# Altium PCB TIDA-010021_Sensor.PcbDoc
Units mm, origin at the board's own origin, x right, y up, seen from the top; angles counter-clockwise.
Board outline 22 x 20 mm, 4 copper layers (Top Layer, Signal Layer 1, Signal Layer 2, Bottom Layer), stack 1.647 mm thick; 35 components, 19 nets, 95 pads, 93 vias.
Unrouted connection lines stored in the file: 42.
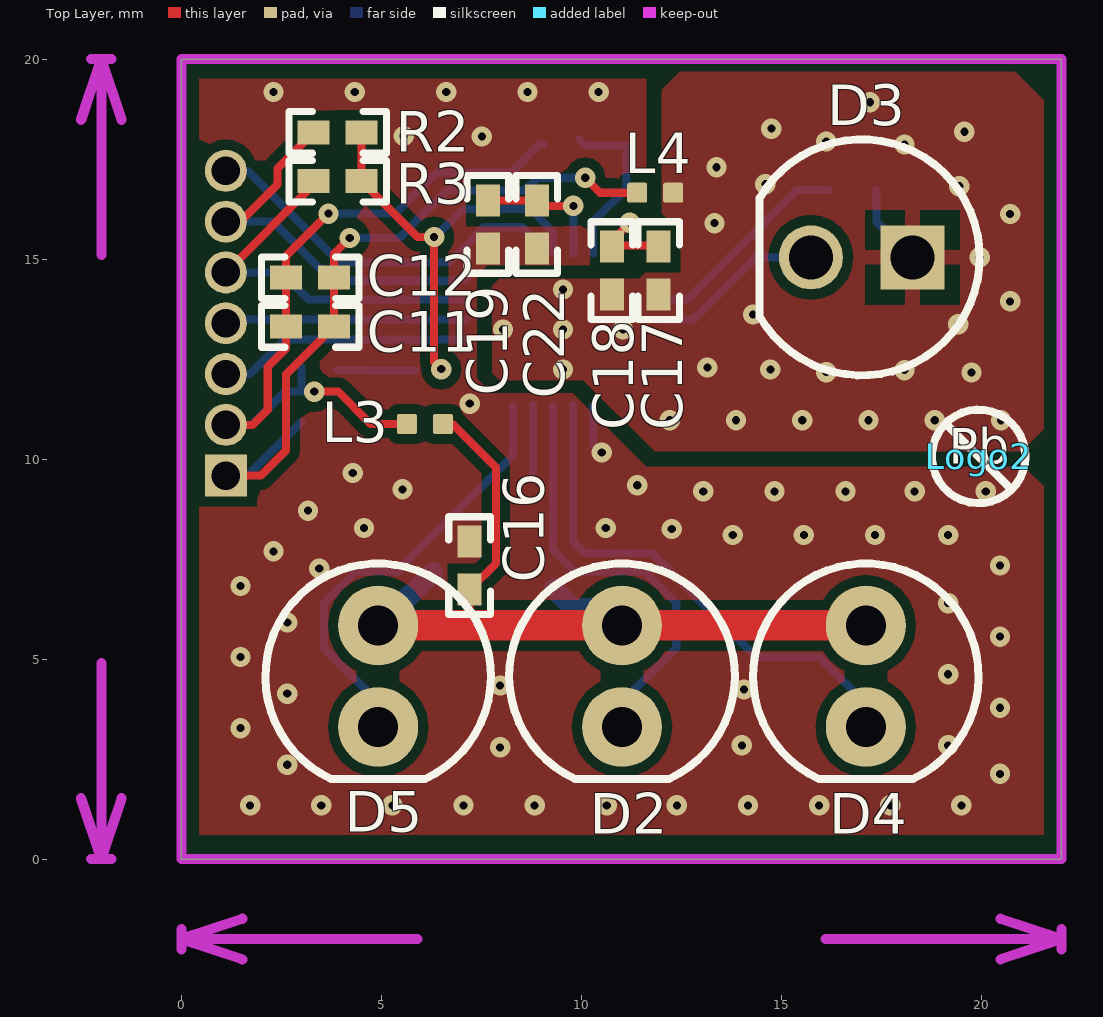
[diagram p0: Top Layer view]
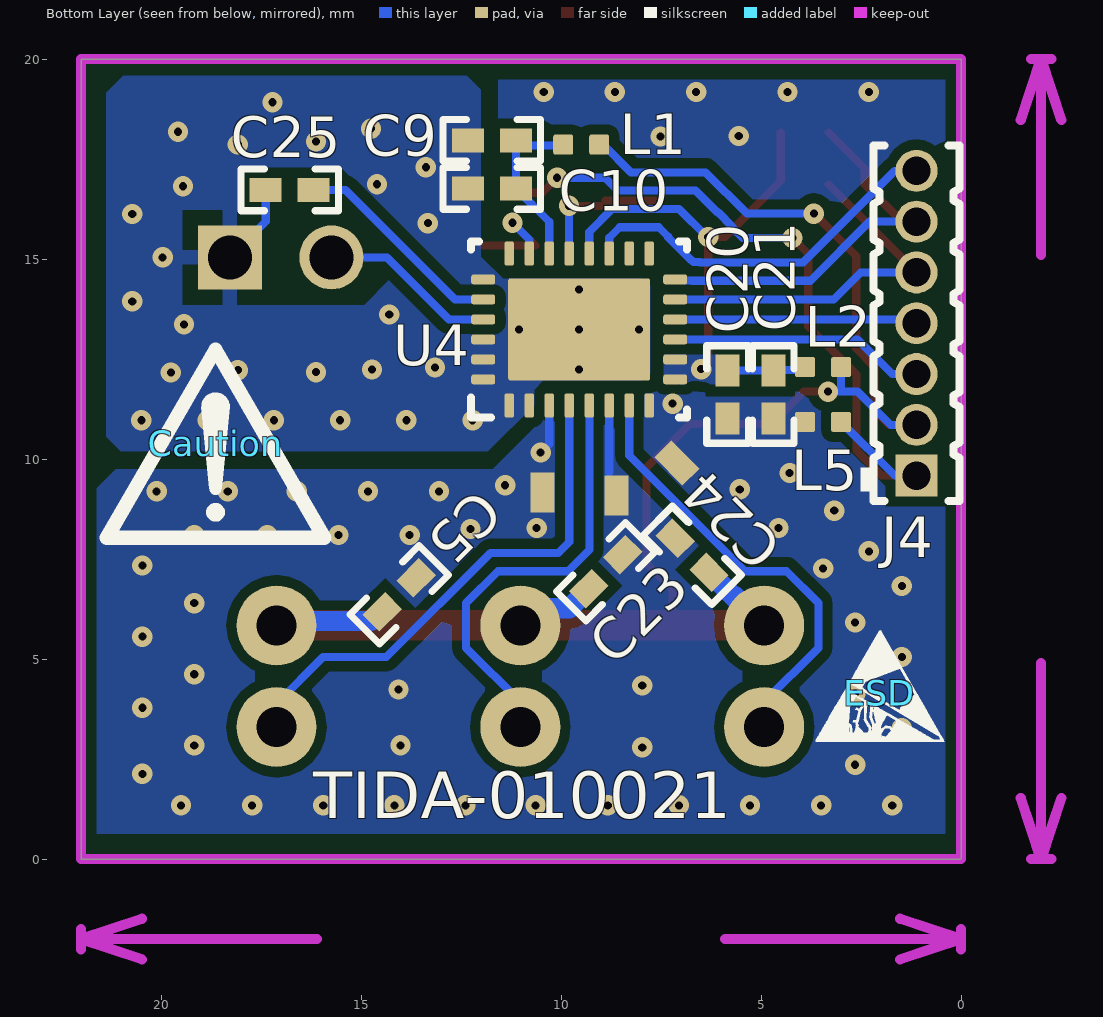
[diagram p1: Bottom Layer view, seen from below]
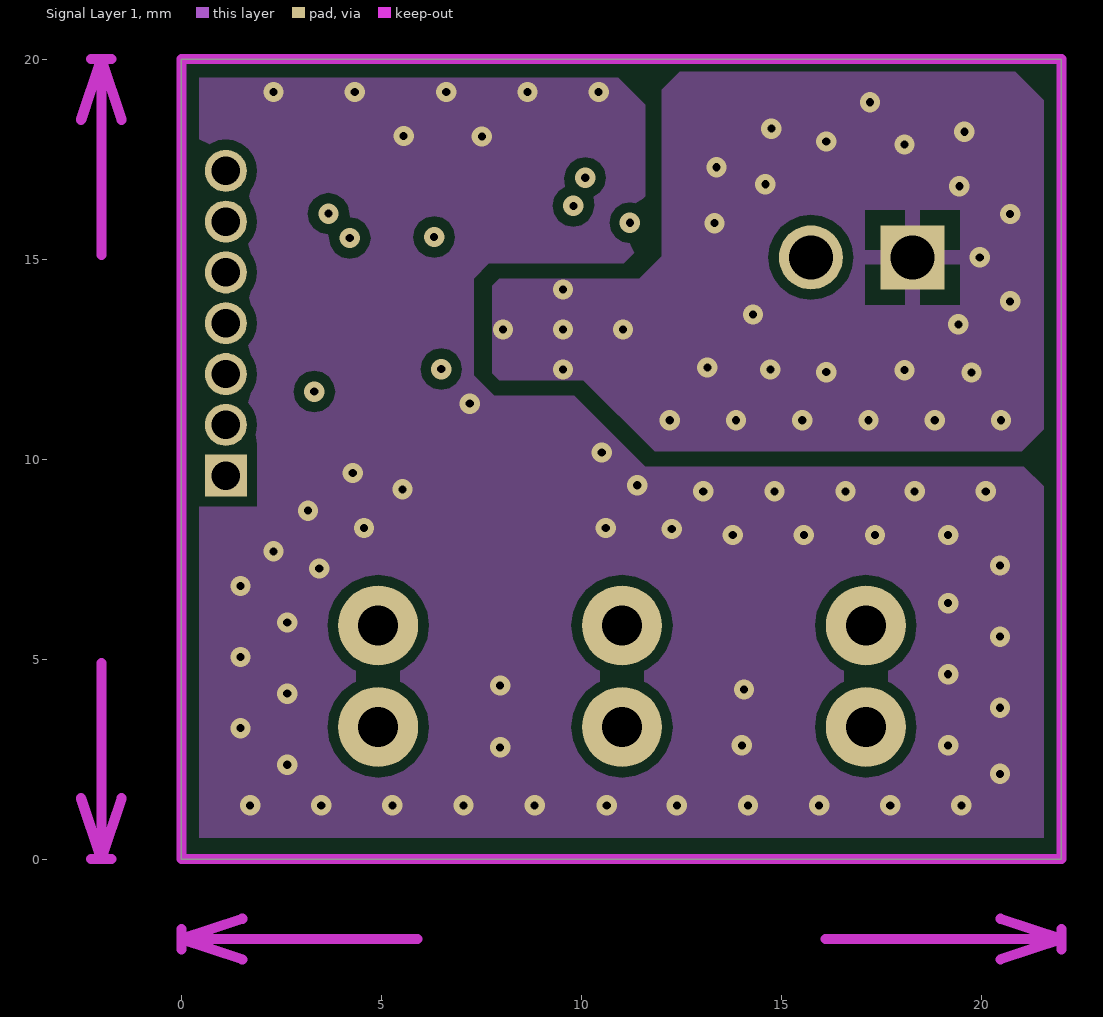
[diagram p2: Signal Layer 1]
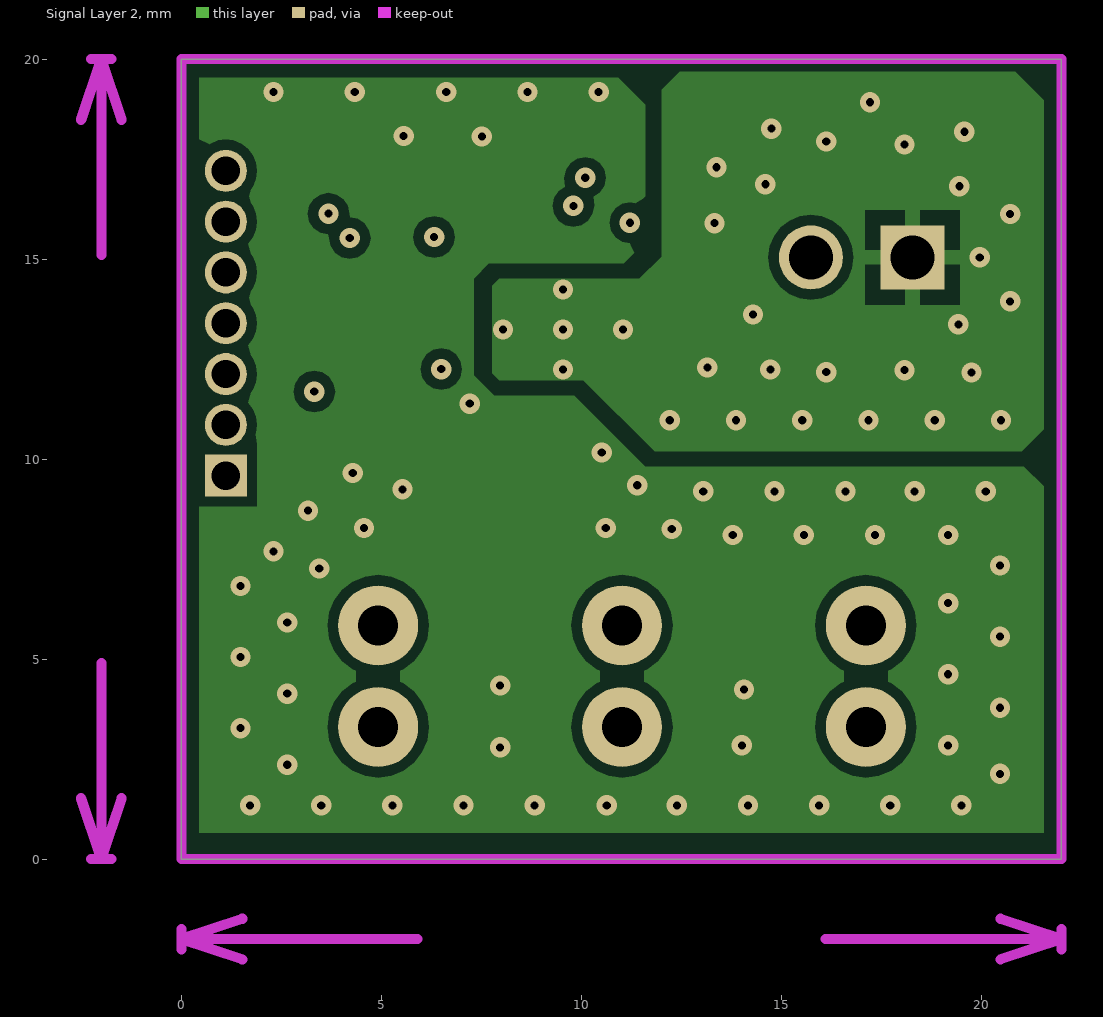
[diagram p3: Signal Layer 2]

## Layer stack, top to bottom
Top Solder: solder mask 0.0102, Solder Resist, Dk 3.5
Top Layer: signal copper 0.0356
Dielectric1: core 1.5037, FR-4, Dk 4.8
Signal Layer 1: signal copper 0.036
Signal Layer 2: signal copper 0.036
Bottom Layer: signal copper 0.0356
Bottom Solder: solder mask 0.0102, Solder Resist, Dk 3.5

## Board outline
0,0 0,20 22,20 22,0

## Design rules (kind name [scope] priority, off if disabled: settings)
AcuteAngle [All] p1: minimum=4.50000000000000E+0001 checktracksonly=FALSE
AssemblyTestPointUsage [All] p1: valid=2
BoardOutlineClearance BoardOutlineClearance_MountingHoles [OnCopper and InComponentClass('Mounting Holes')] p1: gap=1.016
BoardOutlineClearance BoardOutlineClearance_Poly [OnCopper and IsPoly] p2: gap=0.635
BoardOutlineClearance [OnCopper and Not InComponentClass('Logo') and not InComponentClass('FiducialMark') and not InRegion(1000,500,4000,800) and not InPoly] p3: gap=1.905
Clearance Clearance_Keepouts [((IsTrack Or IsArc) And Not InPoly) And IsFree and IsKeepOut vs ((IsTrack Or IsArc) And Not InPoly) And IsFree and IsKeepOut] p1: gap=0.254
Clearance Clearance_Poly [InPolygon] p2: gap=0.254
Clearance [All] p3: gap=0.254
ComponentClearance ComponentClearance_MountingHoles_FiducialMarks [InComponentClass('Mounting Holes') vs InComponentClass('FiducialMark')] p1: gap=1.27 collisioncheckmode=3 verticalgap=0.254 showdistances=FALSE
ComponentClearance ComponentClearance_Shunt [InComponentClass('Header') vs InComponentClass('Shunt')] p2: gap=0 collisioncheckmode=3 verticalgap=0 showdistances=FALSE
ComponentClearance ComponentClearance_Logo [InComponentClass('Logo')] p3: gap=1.27 collisioncheckmode=3 verticalgap=0.254 showdistances=FALSE
ComponentClearance ComponentClearance_ScrewToNut [(HasFootprint('NY PMS 440 0025 PH')) vs (HasFootprint('Keystone_1902C'))] p4: gap=0.127 collisioncheckmode=3 verticalgap=0.254 showdistances=FALSE
ComponentClearance ComponentClearance_MountingHoles [InComponentClass('Mounting Holes')] p5: gap=6.35 collisioncheckmode=3 verticalgap=2540 showdistances=FALSE
ComponentClearance ComponentClearance_SmallPassives [HasFootprint('0201*') or HasFootprint('0402*') or HasFootprint('0508') or HasFootprint('0603*') or HasFootprint('0612') or HasFootprint('0805*') or HasFootprint('0815*') or HasFootprint('0830*') or HasFootprint('1206*') or HasFootprint('1210*') or HasFootprint('1808*') or HasFootprint('1812*') or HasFootprint('1825*') or HasFootprint('2010*') or HasFootprint('2220*') or HasFootprint('2225*') or HasFootprint('2512*') or HasFootprint('2728*') or HasFootprint('3518*') vs HasFootprint('0201*') or HasFootprint('0402*') or HasFootprint('0508') or HasFootprint('0603*') or HasFootprint('0612') or HasFootprint('0805*') or HasFootprint('0815*') or HasFootprint('0830*') or HasFootprint('1206*') or HasFootprint('1210*') or HasFootprint('1808*') or HasFootprint('1812*') or HasFootprint('1825*') or HasFootprint('2010*') or HasFootprint('2220*') or HasFootprint('2225*') or HasFootprint('2512*') or HasFootprint('2728*') or HasFootprint('3518*')] p6: gap=0.38 collisioncheckmode=3 verticalgap=0.254 showdistances=FALSE
ComponentClearance ComponentClearance_THtoSMT [IsThruComponent vs IsSMTComponent] p7: gap=1.016 collisioncheckmode=3 verticalgap=0.762 showdistances=FALSE
ComponentClearance ComponentClearance_THtoTH [IsThruComponent vs IsThruComponent] p8: gap=0.762 collisioncheckmode=3 verticalgap=0.762 showdistances=FALSE
ComponentClearance [All] p9: gap=0.762 collisioncheckmode=3 verticalgap=0.254 showdistances=FALSE
DiffPairsRouting [All] p1: maxlimit=2.54 minlimit=0.254 mostfreqgap=0.254 toplayer_minwidth=0.381 toplayer_maxwidth=0.381 toplayer_prefwidth=0.381 midlayer1_minwidth=0.381 midlayer1_maxwidth=0.381 midlayer1_prefwidth=0.381 midlayer2_minwidth=0.381 midlayer2_maxwidth=0.381 midlayer2_prefwidth=0.381 bottomlayer_minwidth=0.381 bottomlayer_maxwidth=0.381 bottomlayer_prefwidth=0.381 maxuncoupledlength=25.4
FabricationTestPointUsage TestPointUsage [All] p1: valid=2 allowmultiple=FALSE
FabricationTestpoint Testpoint [All] p1: side=3 testpointundercomponent=TRUE minsize=1.016 maxsize=2.54 preferedsize=1.524 minholesize=0 maxholesize=1.016 preferedholesize=0.813 testpointgrid=0.025 allowsidetop=TRUE allowsidebottom=TRUE usegrid=TRUE gridtolerance=0
FanoutControl Fanout_LCC [IsLCC] p1: bgadir=Out bgaviamode=Centered fanoutstyle=Auto fanoutdirection=Alternating viagrid=0.025 // Fanout_LCC (Default Rule)
FanoutControl Fanout_BGA [IsBGA] p2: bgadir=Out bgaviamode=Centered fanoutstyle=Auto fanoutdirection=Alternating viagrid=0.025 // Fanout_BGA (Default Rule)
FanoutControl Fanout_Default [All] p4: bgadir=Out bgaviamode=Centered fanoutstyle=Auto fanoutdirection=Alternating viagrid=0.025 // Fanout_Default (Default Rule)
FanoutControl Fanout_Small [(CompPinCount < 5)] p5: bgadir=Out bgaviamode=Centered fanoutstyle=Auto fanoutdirection=OutThenIn viagrid=0.025 // Fanout_Small (Default Rule)
HoleSize [All] p1: absolutevalues=TRUE maxlimit=6.375 minlimit=0.2 maxpercent=80.000 minpercent=20.000
MinimumAnnularRing MinimumAnnularRing_ThermalPadVias [IsVia and InAnyComponent] p1: minimumring=0.15
MinimumAnnularRing [All] p2: minimumring=0.203
MinimumSolderMaskSliver MinimumSolderMaskSliver_Logo [InComponentClass('Logo') vs InComponentClass('Logo')] p1: minsoldermaskwidth=0.018
MinimumSolderMaskSliver [All] p2: minsoldermaskwidth=0.1
PlaneClearance [All] p1: clearance=0.381
PlaneConnect [All] p1: planeconnectstyle=Relief reliefexpansion=0.254 reliefentries=4 reliefconductorwidth=0.381 reliefairgap=0.381
PolygonConnect PolygonConnect_1 [IsPadHoleValid] p1: connectstyle=Direct reliefconductorwidth=0.381 reliefentries=4 polygonreliefangle="90 Angle" airgapwidth=0.381
PolygonConnect PolygonConnect_Via [IsVia] p2: connectstyle=Direct reliefconductorwidth=0.254 reliefentries=4 polygonreliefangle="90 Angle" airgapwidth=0.254
PolygonConnect [Ispad] p3: connectstyle=Direct reliefconductorwidth=0.381 reliefentries=4 polygonreliefangle="90 Angle" airgapwidth=0.381
RoutingVias ThermalPadVias [IsVia and InAnyComponent] p1: holewidth=0.2 width=0.5 viastyle="Through Hole" minholewidth=0.2 minwidth=0.5 maxholewidth=0.33 maxwidth=0.6
RoutingVias [All] p2: holewidth=0.406 width=0.864 viastyle="Through Hole" minholewidth=0.2 minwidth=0.66 maxholewidth=1.016 maxwidth=1.651
SilkToBoardRegionClearance [Not ((IsComment or IsDesignator) And (Hide <> 'False')) and not InRegion(1000,500,4000,800)] p1:
SilkToSilkClearance SilkToSilkClearance_Pb-FreeLogo [(HasFootprint('Pb-Free_Overlay_Medium') OR HasFootprint('Pb-Free_Overlay_Small')) vs (HasFootprint('Pb-Free_Overlay_Medium') OR HasFootprint('Pb-Free_Overlay_Small'))] p1: silktosilkclearance=0
SilkToSilkClearance [All] p2: silktosilkclearance=0.102
SilkToSolderMaskClearance SilkToComponentPadClearance [(IsPad or IsFill or IsRegion) and InAnycomponent] p1: minsilkscreentomaskgap=0.127 clearancetoexposedcopper=TRUE
SilkToSolderMaskClearance "Silk to Solder Mask Opening" [All] p2: minsilkscreentomaskgap=0.102 clearancetoexposedcopper=FALSE
SolderMaskExpansion [All] p1: expansion=0.05
Width [All] p1: maxlimit=2.54 minlimit=0.152 preferedwidth=0.254 checkconnectedcopper=TRUE
14 further rules are at their usual default settings.

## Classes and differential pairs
component class Header: J4
component class TIDA-010021_Sensor: C5 C9 C10 C11 C12 C16 C17 C18 C19 C20 C21 C22 C23 C24 C25 D2 D3 D4 D5 J4 L1 L2 L3 L4 L5 R2 R3 U4
component class TIDA-010021_Sensor_Hardware: Caution ESD Logo2 ZZ1 ZZ2 ZZ3 ZZ4
component class AssemblyNote: ZZ1 ZZ2 ZZ3 ZZ4

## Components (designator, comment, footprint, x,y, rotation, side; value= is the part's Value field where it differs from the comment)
C5 "885012205037" 0402 14.046,6.604 r135 bottom
C9 "885012205037" 0402 11.729,17.967 r0 bottom
C10 "GRM155R61A105KE15D" 0402 11.73,16.765 r0 bottom
C11 "885012205037" 0402 3.219,13.316 r0 top
C12 "GRM155R61A105KE15D" 0402 3.219,14.535 r0 top
C16 "GRM155R61A105KE15D" 0402 7.207,7.337 r90 top
C17 "885012205037" 0402 11.933,14.712 r90 top
C18 "GRM155R61A105KE15D" 0402 10.765,14.712 r90 top
C19 "GRM155R61A105KE15D" 0402 7.666,15.865 r90 top
C20 "885012205037" 0402 5.837,11.613 r90 bottom
C21 "GRM155R61A105KE15D" 0402 4.694,11.613 r90 bottom
C22 "885012205037" 0402 8.887,15.865 r90 top
C23 "885012205037" 0402 8.883,7.185 r135 bottom
C24 "885012205037" 0402 6.724,7.591 r45 bottom
C25 "GRM1555C1E6R2CA01D" 0402 16.783,16.729 r0 bottom
Caution "CAUTION.  READ USER GUIDE BEFORE USE" IEC_Caution_small 18.637,10.395 r180 bottom
D2 "SFH 4556" SFH4556 11.017,4.569 r270 top
D3 "SFH 213" SFH_213 17.009,15.042 r180 top
D4 "SFH 4556" SFH4556 17.113,4.569 r270 top
D5 "SFH 4556" SFH4556 4.921,4.569 r270 top
ESD "ESD Susceptible" ESD_Overlay_small 2.051,4.156 r180 bottom
J4 "FTS-107-01-F-S" Samtec_FTS-107-01-x-S 1.113,13.395 r90 bottom
L1 "MMZ1005S182ET000" MMZ1005-E 9.495,17.862 r0 bottom
L2 "MMZ1005S182ET000" MMZ1005-E 3.449,12.299 r0 bottom
L3 "MMZ1005S182ET000" MMZ1005-E 6.091,10.877 r0 top
L4 "MMZ1005S182ET000" MMZ1005-E 11.848,16.658 r0 top
L5 "MMZ1005S182ET000" MMZ1005-E 3.449,10.927 r0 bottom
Logo2 "Pb-Free Symbol" Pb-Free_Overlay_Small 19.932,10.064 r0 top
R2 "RC0402FR-072K2L" 0402 3.907,18.166 r180 top
R3 "RC0402FR-072K2L" 0402 3.907,16.947 r180 top
U4 "OPT3101RHFR" RHF0028A 9.545,13.239 r90 bottom
ZZ1 "This Assembly Note is for PCB labels only" AssemblyNoteLabel -5.027,66.785 r0 top
ZZ2 "These assemblies are ESD sensitive, ESD precautions shall be observed." AssemblyNote -5.027,64.02 r0 top
ZZ3 "These assemblies must be clean and free from flux and all contaminants. Use of no clean flux is not acceptable." AssemblyNote -5.027,61.77 r0 top
ZZ4 "These assemblies must comply with workmanship standards IPC-A-610 Class 2, unless otherwise specified." AssemblyNote -5.027,59.521 r0 top

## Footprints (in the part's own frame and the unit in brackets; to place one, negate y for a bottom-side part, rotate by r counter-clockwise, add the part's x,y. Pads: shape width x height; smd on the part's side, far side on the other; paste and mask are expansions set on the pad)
0402 [mm] "0402 from SM-752 data"
  rect 0.8x0.6 smd: 1(-0.6,0) 2(0.6,0)
  silkscreen extent -1.22,-0.52 1.22,0.52, body extent -0.55,-0.3 0.55,0.3, height 0.6
AssemblyNote [mm] "Assembly Note"
AssemblyNoteLabel [mm] "Assembly Note for PCB Labels"
ESD_Overlay_small [mm]
  silkscreen extent -1.58,-1.23 1.62,1.55
IEC_Caution_small [mm]
  silkscreen extent -2.72,-2.36 2.72,2.35
MMZ1005-E [mm] "SMD, 2-Leads, Body 1x0.5mm"
  rrect20% 0.5x0.5 smd: 1(-0.45,0) 2(0.45,0)
  body extent -0.53,-0.28 0.53,0.28, height 0.55
Pb-Free_Overlay_Small [mm]
  silkscreen extent -1.16,-1.17 1.17,1.17
RHF0028A [mm] "QFN, 28-Leads, Body 5x4mm, Pitch 0.5mm, Thermal Pad 3.55x2.55mm"
  rrect42% 0.6x0.24 smd: 1(-1.9,1.75) 2(-1.9,1.25) 3(-1.9,0.75) 4(-1.9,0.25) 5(-1.9,-0.25) 6(-1.9,-0.75) 7(-1.9,-1.25) 8(-1.9,-1.75) 15(1.9,-1.75) 16(1.9,-1.25) 17(1.9,-0.75) 18(1.9,-0.25) 19(1.9,0.25) 20(1.9,0.75) 21(1.9,1.25) 22(1.9,1.75)
  rrect42% 0.24x0.6 smd: 9(-1.25,-2.4) 10(-0.75,-2.4) 11(-0.25,-2.4) 12(0.25,-2.4) 13(0.75,-2.4) 14(1.25,-2.4) 23(1.25,2.4) 24(0.75,2.4) 25(0.25,2.4) 26(-0.25,2.4) 27(-0.75,2.4) 28(-1.25,2.4)
  rrect9% 1.13x1.53 on Bottom Paste: 29(-0.665,-0.865) 29(-0.665,0.865) 29(0.665,-0.865) 29(0.665,0.865)
  rrect4% 2.55x3.55 smd paste-3.55: 29(0,0)
  silkscreen extent -2.2,-2.7 2.2,2.7, body extent -2,-2.5 2,2.5, height 1
Samtec_FTS-107-01-x-S [mm] "Header, 1.27 mm, 7x1, TH"
  rect 1.05x1.05 hole 0.71: 1(-3.81,0)
  round 1.05 hole 0.71: 2(-2.54,0) 3(-1.27,0) 4(0,0) 5(1.27,0) 6(2.54,0) 7(3.81,0)
  silkscreen extent -4.45,-1.08 4.45,1.4, body extent -4.44,-1.08 4.45,1.08, height 3.91
SFH4556 [mm] "TH, 2-Leads, Dia 5.5mm, Pin Spacing 2.54mm"
  round 2 hole 1: 1(-1.27,0) 2(1.27,0)
  silkscreen extent -2.82,-2.82 2.57,2.82, body extent -2.75,-2.75 2.5,2.75, height 10.7
SFH_213 [mm] "TH, 2-Leads, Dia 5.7mm, Pin Spacing 2.54mm"
  rect 1.6x1.6 hole 1.1: 1(-1.27,0)
  round 1.6 hole 1.1: 2(1.27,0)
  silkscreen extent -2.95,-2.95 2.55,2.95, body extent -2.95,-2.95 2.55,2.95, height 11.4

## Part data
C5 C9 C11 C17 C20 C22 C23 C24: "CAP, CERM, 0.1 μF, 16 V, +/- 10%, X7R, 0402"
C10 C12 C16 C18 C19 C21: "CAP, CERM, 1 μF, 10 V, +/- 10%, X5R, 0402"
C25: "CAP, CERM, 6.2 pF, 25 V, +/- 5%, C0G/NP0, 0402"
Caution: library part IEC_Caution, "IEC 61010-1 Caution Warning"
D2 D4 D5: library part CMP-0077984-1, "LED, Infrared, TH"
D3: "Silicon PIN Photodiode, TH"
ESD: library part ESD_Susceptible, "ESD Susceptible Symbol"
J4: library part CMP-0075532-1, "Header, 1.27mm, 7x1, Gold, TH"
L1 L2 L3 L4 L5: library part CMP-0080017-1, "Inductor, Ferrite Bead, Ferrite, 0.2 A, 2.1 ohm, SMD"
Logo2: library part Pb-Free
R2 R3: "RES, 2.20 k, 1%, 0.063 W, 0402"
U4: library part CMP-0074632-3, "Long Range Proximity/Depth Sensor, RHF0028A (VQFN-28)"
ZZ1: library part AssemblyNoteLabel
ZZ2 ZZ3 ZZ4: library part AssemblyNote

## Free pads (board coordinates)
  rect 0.6x1 smd far side rot 135: 2(7.105,9.903)
  rect 0.6x1 smd far side: 2(8.611,9.093) 3(10.458,9.166)

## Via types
v1: diameter 0.508, hole 0.203, Top Layer to Bottom Layer, 80 vias
v2: diameter 0.508/0.508/0.508/0.508 (per signal layer), hole 0.203, Top Layer to Bottom Layer, 8 vias
v3: diameter 0.5, hole 0.2, Top Layer to Bottom Layer, 5 vias

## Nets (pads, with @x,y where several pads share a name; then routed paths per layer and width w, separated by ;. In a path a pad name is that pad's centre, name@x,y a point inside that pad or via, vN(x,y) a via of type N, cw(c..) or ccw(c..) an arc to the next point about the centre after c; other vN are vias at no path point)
AVDD_3V3: C9.1 C10.1 L1.2 U4.20 | length 4.3
  Bottom Layer w0.203: L1.2@9.945,17.989 10.097,17.836 11.129,17.836 C10.1 ; U4.20 10.295,15.931 C10.1
AVSS: C9.2 C10.2 C17.1 C18.1 C25.2 D3.1 L4.2 U4.1 U4.2 U4.23 U4.26 U4.27 U4.28 U4.29@9.545,13.239 | length 2.1
  Bottom Layer w0.203: C25.2 17.383,15.938 D3.1
  other v1: 12.211,10.969 13.867,10.969 15.523,10.969 17.179,10.969 18.835,10.969 20.491,10.969 16.124,12.172 19.754,12.163 18.08,12.223 14.725,12.239 13.15,12.29 19.426,13.366 14.293,13.611 20.72,13.941 19.959,15.042 13.328,15.897 20.72,16.126 19.451,16.82 14.6,16.871 13.379,17.294 18.08,17.862 16.124,17.938 19.577,18.183 14.751,18.259 17.214,18.92
  other v3: 9.545,12.239 8.045,13.239 9.545,13.239 11.045,13.239 9.545,14.239
GP1: J4.3 U4.11 | length 6.4
  Bottom Layer w0.203: J4.3 1.72,12.125 2.584,12.989 U4.11
GP2: J4.4 U4.12 | length 5.9
  Bottom Layer w0.203: J4.4@1.207,13.489 U4.12
IOVDD: C20.2 C21.2 L2.2 R2.1 R3.1 U4.9 U4.10 U4.18 | length 13.3
  Top Layer w0.203: R2.1 R3.1 5.904,15.55 v1(6.32,15.55) 6.32,12.426 v1(6.497,12.248) 6.599,12.35 v1@6.548,12.401
  Bottom Layer w0.203: L2.2@3.899,12.223 C21.2@4.684,12.223 ; C21.2 C20.2 ; v1(6.32,15.55) 6.345,15.55 7.046,16.252 8.722,16.252 9.295,15.679 U4.18 U4.18@9.295,15.268
IOVSS: C5.2 C16.2 C19.1 C20.1 C21.1 C22.1 C23.2 C24.2 L5.2 pad.2 pad.3 U4.3 U4.6 U4.8 | length 2.9
  Bottom Layer w0.203: 8.795,9.662 8.795,10.406 U4.6 ; U4.3 10.295,10.381 v1(10.511,10.165)
  other v1: 1.72,1.343 3.498,1.343 5.276,1.343 7.054,1.343 8.832,1.343 10.636,1.343 12.388,1.343 14.166,1.343 15.944,1.343 17.722,1.343 19.5,1.343 20.466,2.13 2.648,2.357 7.969,2.791 14.014,2.841 19.17,2.841 1.48,3.271 20.466,3.781 2.648,4.135 14.065,4.238 7.969,4.34 19.17,4.619 1.48,5.049 20.466,5.559 2.648,5.913 19.17,6.397 1.48,6.827 3.448,7.261 20.466,7.337 2.305,7.693 13.785,8.099 15.563,8.099 17.341,8.099 19.17,8.099 12.261,8.252 10.61,8.277 3.168,8.709 13.049,9.191 14.827,9.191 16.605,9.191 18.332,9.191 20.11,9.191 5.53,9.242 11.398,9.344 4.286,9.649 7.209,11.385
  other v2: 4.565,8.277 5.558,18.078 7.513,18.065 2.305,19.174 4.337,19.174 6.623,19.174 8.655,19.174 10.433,19.174
NetC17_2: C17.2 C18.2 U4.21 | length 3
  Top Layer w0.203: v1(11.212,15.906) 10.644,15.337 C17.2@11.95,15.337
  Bottom Layer w0.203: U4.21 10.795,15.489 v1(11.212,15.906)
NetC19_2: C19.2 C22.2 U4.19 | length 3.2
  Top Layer w0.203: C19.2 C22.2 ; C22.2@9.024,16.328 v1(9.799,16.328)
  Bottom Layer w0.203: U4.19 9.799,15.143 v1(9.799,16.328)
NetC25_1: C25.1 U4.24 | length 5.4
  Bottom Layer w0.203: U4.24 12.653,13.989 15.393,16.729 C25.1
NetD2_2: D2.2 U4.5 | length 10.9
  Bottom Layer w0.203: U4.5 9.29,11.333 9.29,7.732 9.827,7.194 11.578,7.194 12.372,6.4 12.372,5.277 11.017,3.921 D2.2
NetD3_2: D3.2 U4.25 | length 4.4
  Bottom Layer w0.203: U4.25 12.8,13.489 13.903,14.592 14.353,15.042 D3.2
NetD4_2: D4.2 U4.4 | length 13
  Bottom Layer w0.203: U4.4 9.795,7.924 10.068,7.651 11.768,7.651 14.37,5.049 15.946,5.049 17.113,3.883 D4.2
NetD5_2: D5.2 U4.7 | length 11.2
  Bottom Layer w0.203: D5.2 4.921,3.921 3.565,5.277 3.565,6.4 4.359,7.194 5.446,7.194 5.449,7.198 5.449,7.243 8.295,10.089 U4.7
SCL: J4.5 R3.2 U4.13 | length 9.4
  Top Layer w0.203: J4.5 R3.2@3.307,16.859
  Bottom Layer w0.203: J4.5 2.506,14.665 3.182,13.989 U4.13
SDA: J4.6 R2.2 U4.14 | length 10
  Top Layer w0.203: J4.6 1.479,15.935 2.406,16.862 2.406,17.266 R2.2
  Bottom Layer w0.203: J4.6 2.288,15.935 3.764,14.458 6.721,14.458 6.728,14.464 6.888,14.464 6.913,14.489 U4.14
VDD_3V3: C11.1 C12.1 J4.2 L1.1 L2.1 L3.1 | length 18.6
  Top Layer w0.203: J4.2 1.783,10.855 2.159,11.23 2.159,12.302 2.619,12.762 C11.1 C12.1 2.619,15.075 v1(3.678,16.134) ; v1(3.324,11.685) 3.922,11.685 4.731,10.877 L3.1
  Bottom Layer w0.203: J4.2 1.758,10.855 2.589,11.685 v1(3.324,11.685) ; 2.999,11.694 L2.1 ; v1(3.678,16.134) 5.354,16.134 6.386,17.166 8.25,17.166 8.946,17.862 L1.1
VDDL: C5.1 C16.1 C23.1 C24.1 D2.1 D4.1 D5.1 L3.2 | length 25.8
  Top Layer w0.203: L3.2 6.778,10.877 7.864,9.79 7.862,9.789 7.862,7.39 C16.1@7.21,6.737 ; 7.207,5.864 C16.1
  Top Layer w0.762: D5.1 D2.1 D4.1
  Bottom Layer w0.508: 5.657,6.575 D5.1 4.972,5.839 C24.1 ; C23.1 9.798,6.27 10.585,6.27 D2.1 ; C5.1@14.751,5.95 D4.1@17.002,5.95 ; D4.1@16.875,5.6 D4.1
VSS_IN: C11.2 C12.2 J4.1 L4.1 L5.1 | length 18.2
  Top Layer w0.203: J4.1 1.987,9.585 2.616,10.214 2.616,12.112 3.163,12.66 3.166,12.66 3.819,13.313 C11.2 C12.2 3.819,15.132 v1(4.211,15.525) ; v1(10.097,17.031) 10.47,16.658 L4.1
  Bottom Layer w0.203: J4.1 1.657,9.585 L5.1 ; v1(4.211,15.525) 5.457,15.525 5.71,15.777 5.71,15.803 6.067,16.16 6.092,16.16 6.641,16.709 8.58,16.709 8.902,17.031 v1(10.097,17.031)
VSYNC_RST: J4.7 U4.17 | length 9.5
  Bottom Layer w0.203: J4.7 1.664,17.205 3.954,14.915 6.532,14.915 6.538,14.922 6.685,14.922 6.728,14.964 6.742,14.964 7.32,15.542 7.32,15.556 7.558,15.794 8.533,15.794 8.795,15.532 U4.17
pads on no net: U4.15 U4.16 U4.22 U4.29@8.68,12.574 U4.29@8.68,13.904 U4.29@10.41,12.574 U4.29@10.41,13.904

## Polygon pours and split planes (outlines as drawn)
AVSS on Bottom Layer "BOTTOM_LAYER_AVSS_P252" (solid, remove dead copper, pour order 252): 7.767,14.331 7.945,14.509 11.45,14.509 12.009,15.062 12.009,19.226 12.363,19.58 20.948,19.58 21.371,19.157 21.371,10.554 21.008,10.191 11.831,10.191 10.675,11.347 10.675,11.736 10.443,11.969 10.053,11.969 7.945,11.969 7.767,12.147 7.767,14.331 7.945,14.509
IOVSS on Bottom Layer "BOTTOM_LAYER_IOVSS_P254" (solid, remove dead copper, pour order 254): 21.609,0.632 21.609,9.268 21.133,9.744 20.72,9.744 11.703,9.744 9.798,11.649 7.766,11.649 7.385,12.03 7.385,14.57 7.639,14.824 11.065,14.824 11.576,15.335 11.576,19.478 0.4,19.478 0.4,0.632
IOVDD on Bottom Layer "BOTTOM_LAYER_IOVDD_P256" (solid, pour order 256): 7.412,12.604 7.437,12.578 7.437,11.893 7.412,11.867 7.386,11.867 6.015,11.867 5.939,11.943 5.939,12.502 6.04,12.604
IOVSS on Top Layer "TOP_LAYER_IOVSS_P272" (solid, remove dead copper, pour order 272): 0.452,0.606 21.56,0.606 21.56,9.317 21.066,9.81 11.626,9.81 9.787,11.649 7.757,11.649 7.385,12.021 7.385,14.583 7.65,14.849 11.023,14.849 11.626,15.446 11.626,19.504 0.452,19.504
AVSS on Top Layer "TOP_LAYER_AVSS_P274" (solid, remove dead copper, pour order 274): 7.767,14.331 7.945,14.509 11.45,14.509 12.004,15.062 12.011,19.228 12.465,19.682 20.847,19.682 21.56,18.969 21.56,10.743 21.008,10.191 11.831,10.191 10.053,11.969 7.945,11.969 7.767,12.147
AVSS on Signal Layer 1 "SIGNAL_LAYER_1_AVSS_P288" (solid, remove dead copper, pour order 288): 7.767,14.331 7.945,14.509 11.45,14.509 12.009,15.068 12.009,19.226 12.465,19.682 20.846,19.682 21.56,18.969 21.56,10.743 21.008,10.191 11.831,10.191 10.053,11.969 7.945,11.969 7.767,12.146
IOVSS on Signal Layer 1 "SIGNAL_LAYER_1_IOVSS_P290" (solid, remove dead copper, pour order 290): 21.56,0.53 21.56,9.317 21.066,9.81 11.603,9.81 9.825,11.588 7.818,11.588 7.31,12.096 7.31,14.509 7.691,14.89 11.065,14.89 11.598,15.423 11.603,18.852 10.926,19.529 0.452,19.529 0.452,0.53
IOVSS on Signal Layer 2 "SIGNAL_LAYER_2_IOVSS_P304" (solid, remove dead copper, pour order 304): 0.452,0.657 21.56,0.657 21.56,9.317 21.066,9.81 11.603,9.81 9.825,11.588 7.818,11.588 7.31,12.096 7.31,14.509 7.691,14.89 11.065,14.89 11.598,15.423 11.603,18.852 10.926,19.529 0.452,19.529
AVSS on Signal Layer 2 "SIGNAL_LAYER_2_AVSS_P306" (solid, remove dead copper, pour order 306): 21.008,10.191 21.56,10.743 21.56,18.969 20.847,19.682 12.465,19.682 12.009,19.226 12.009,15.062 11.45,14.509 7.945,14.509 7.767,14.331 7.767,12.147 7.945,11.969 10.053,11.969 11.831,10.191

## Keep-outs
Keep-Out Layer:
  lines w0.254: -2.508,1.524 -2,0 ; -2.508,18.476 -2,20 ; -2.254,0 -1.746,0 ; -2.254,20 -1.746,20 ; -2,4.896 -2,0 ; -2,15.104 -2,20 ; -1.492,1.524 -2,0 ; -1.492,18.476 -2,20 ; 0,-2.254 0,-1.746 ; 1.524,-2.508 0,-2 ; 1.524,-1.492 0,-2 ; 5.896,-2 0,-2 ; 16.104,-2 22,-2 ; 20.476,-2.508 22,-2 ; 20.476,-1.492 22,-2 ; 22,-2.254 22,-1.746 ; 0,0 0,20 22,20 22,0 0,0
  text "20 (mm)" at -1.086,5.15 h1.52 r90
  text "22 (mm)" at 6.15,-2.914 h1.52
  text ".Layer_Name" at 4.929,-55.046 h1.52

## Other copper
Bottom Layer:
  pour cut-out: 14.926,13.861 14.282,14.505 14.282,16.057 15.504,17.279 17.934,17.279 18.078,17.135 18.078,13.861

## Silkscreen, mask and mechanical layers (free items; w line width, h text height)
Top Overlay:
  text ".Layer_Name" at 4.929,-55.046 h1.52
Bottom Overlay:
  text "TIDA-010021" at 16.198,0.632 h2
  text ".Layer_Name" at 4.929,-55.046 h1.52
Top Paste:
  text ".Layer_Name" at 4.929,-55.046 h1.52
Bottom Paste:
  text "This document can handle board shapes up to 7.9in x 10in, although" at 144.452,30.895 h1.52
  text "our panel vendors top out at 7in x 10in." at 144.452,27.744 h1.52
  text "To re-size the board shape, do the following:" at 145.849,24.593 h1.52
  text "Select lines on M1 Board Outline and delete (easy in single layer mode...shift+s)" at 147.373,21.442 h1.52
  text "Draw a rectangle using lines (example will be for a 4\" x 6\" board" at 147.373,18.291 h1.52
  text "Enter Place Line mode (keyboard pl)" at 152.707,15.14 h1.52
  text "keyboard jo to jump to origin, hit enter" at 152.707,11.989 h1.52
  text "keyboard jl to jump to location, set x to 6000, hit enter twice" at 152.707,8.838 h1.52
  text "keyboard jl to jump to location, set x to 6000 and y to 4000, hit enter twice" at 152.707,5.686 h1.52
  text "keyboard jl to jump to location, set x to 0 and y to 4000, hit enter twice" at 152.707,2.535 h1.52
  text "keyboard jo to jump to origin, hit enter" at 152.707,-0.616 h1.52
  text "Hit ESC twice to exit place line mode" at 152.707,-3.767 h1.52
  text "Select lines on M1 Board Outline" at 147.373,-7.426 h1.52
  text "Menu Design|Board Shape|Define from Selected Objects (keyboard dsd)" at 147.373,-10.069 h1.52
  text "If you re-size the board, don't forget to move the drill table strings on the" at 144.452,-18.178 h1.52
  text "Drill Drawing Layer...they should be just to the right of your board shape" at 149.354,-20.87 h1.52
  text ".Layer_Name" at 4.929,-55.046 h1.52
Top Solder:
  circle w1.4: c17.009,15.042 r3.7
  text ".Layer_Name" at 4.929,-55.046 h1.52
  text ".Layer_Name" at 4.929,-55.046 h1.52
Bottom Solder:
  text ".Layer_Name" at 4.929,-55.046 h1.52
M1 Board Outline:
  circle w0.006: c-14.903,-24.403 r0.003
  circle w0.006: c-14.903,-24.403 r0.003
  circle w0.006: c10.066,-22.735 r0.003
  circle w0.006: c10.066,-22.735 r0.003
  circle w0.006: c-0.732,1.053 r0.003
  circle w0.006: c-0.232,1.053 r0.003
  circle w0.006: c-1.402,2.088 r0.003
  circle w0.006: c11.713,-0.613 r0.003
  circle w0.006: c23.24,2.413 r0.003
  circle w0.006: c11.713,-0.613 r0.003
  text ".Layer_Name" at 4.929,-55.046 h1.52
M2 Board Dimensions:
  rectangle: -9.726,-40.225 -6.551,-37.05
  rectangle: -6.551,-43.4 2.974,-40.225
  lines w0.178: -9.726,-40.225 15.674,-40.225 ; -6.551,-43.4 -6.551,-37.05 ; -3.376,-43.4 -3.376,-37.05 ; 2.974,-43.4 2.974,-37.05 ; 9.324,-43.4 9.324,-37.05 ; -9.726,-43.4 15.674,-43.4 15.674,-37.05 -9.726,-37.05 -9.726,-43.4
  text ".Layer_Name" at 4.929,-55.046 h1.52
M3 3D STEP Top:
  text ".Layer_Name" at 4.929,-55.046 h1.52
M4 3D STEP Bottom:
  text ".Layer_Name" at 4.929,-55.046 h1.52
M5 Assembly Top:
  lines w0.254: -17.143,-56.866 150.497,-56.866 ; -17.143,-51.701 150.548,-51.701 ; -17.143,-46.537 -17.143,-62.031 84.584,-62.031 150.548,-62.031 150.548,-46.537 -17.13,-46.537 -17.13,-62.031 22.887,-62.031 ; 45.468,-62.031 45.468,-46.537 ; 77.65,-51.701 77.65,-46.537 ; 98.986,-51.701 98.986,-46.537 ; 114.784,-62.196 114.784,-57.044
  text "COMPONENTS MARKED 'DNP' SHOULD NOT BE POPULATED." at 19.573,-41.33 h1.52
  text "ASSEMBLY VARIANT:" at 19.56,-44.263 h1.52
  text ".VariantName" at 45.874,-44.263 h1.52
  text "PCB VIEWED FROM TOP SIDE" at -15.53,-49.894 h1.52
  text "BOARD #:" at 47.373,-49.894 h1.52
  text ".PRJ_Number" at 61.229,-49.894 h1.52
  text "REV:" at 82.679,-49.894 h1.52
  text ".PCB_Rev" at 90.083,-49.894 h1.52
  text "SVN REV:" at 103.964,-49.894 h1.52
  text ".VersionControl_RevNumber" at 116.816,-49.894 h1.52
  text "TID #:" at 47.373,-55.058 h1.52
  text ".TID" at 61.229,-55.058 h1.52
  text "PLOT NAME =" at -15.53,-60.274 h1.52
  text ".plot_File_Name" at 4.929,-60.274 h1.52
  text "GENERATED    :" at 47.424,-60.274 h1.52
  text ".Print_Date" at 69.509,-60.274 h1.52
  text ".Print_Time" at 88.026,-60.274 h1.52
  text "TEXAS INSTRUMENTS" at 120.144,-60.274 h1.52
M6 Assembly Bottom:
  lines w0.254: -17.156,-51.714 150.535,-51.714 ; -17.105,-56.879 150.535,-56.879 ; 18.607,-62.209 18.607,-57.057 ; 34.406,-51.714 34.406,-46.549 ; 55.742,-51.714 55.742,-46.549 ; 87.924,-62.043 87.924,-46.549 ; 110.505,-62.043 150.522,-62.043 150.522,-46.549 -17.156,-46.549 -17.156,-62.043 48.808,-62.043 150.535,-62.043 150.535,-46.549
  text "PCB VIEWED FROM BOTTOM SIDE" at 93.347,-35.373 h1.52 r180
  text "COMPONENTS MARKED 'DNP' SHOULD NOT BE POPULATED." at 145.264,-41.317 h1.52
  text ".VariantName" at 118.747,-44.263 h1.52
  text "ASSEMBLY VARIANT:" at 145.137,-44.263 h1.52
  text ".VersionControl_RevNumber" at 16.575,-49.906 h1.52
  text "SVN REV:" at 29.428,-49.906 h1.52
  text ".PCB_Rev" at 43.309,-49.906 h1.52
  text "REV:" at 50.713,-49.906 h1.52
  text ".PRJ_Number" at 72.163,-49.906 h1.52
  text "BOARD #:" at 86.019,-49.906 h1.52
  text ".TID" at 72.163,-55.071 h1.52
  text "TID #:" at 86.019,-55.071 h1.52
  text "TEXAS INSTRUMENTS" at 13.248,-60.287 h1.52
  text ".Print_Time" at 45.366,-60.287 h1.52
  text ".Print_Date" at 63.883,-60.287 h1.52
  text "GENERATED    :" at 85.968,-60.287 h1.52
  text ".plot_File_Name" at 128.462,-60.287 h1.52
  text "PLOT NAME =" at 148.922,-60.287 h1.52
M9 Title Sheet:
  drawing of 57 lines, arcs and shapes, not listed
  text "1" at 9.065,170.887 h1.78
  text "2" at 72.455,170.887 h1.78
  text "3" at 135.685,170.887 h1.78
  text "4" at 199.354,170.887 h1.78
  text "5" at 262.828,170.887 h1.78
  text "6" at 326.455,170.887 h1.78
  text "A" at -20.305,141.855 h1.78
  text "A" at 355.615,141.855 h1.78
  text "B" at -20.305,81.403 h1.78
  text "B" at 355.615,81.403 h1.78
  text "C" at -20.305,21.078 h1.78
  text "C" at 355.615,21.078 h1.78
  text "PROJECT TITLE:" at 278.399,-26.191 h1.14
  text ".PRJ_Title" at 279.669,-29.578 h1.78
  text "DESIGNED FOR:" at 278.399,-33.837 h1.14
  text ".PRJ_Customer" at 279.669,-37.393 h1.78
  text "D" at -20.305,-39.12 h1.78
  text "D" at 355.615,-39.12 h1.78
  text "FILE NAME:" at 278.399,-41.457 h1.14
  text ".PCB_File_Name_No_Path" at 279.669,-44.505 h1.78
  text "Texas Instruments (TI) and/or its licensors do not warrant the accuracy or completeness of this specification" at 152.173,-48.615 h1.14
  text "ENGINEER:" at 278.399,-48.823 h1.14
  text "LAYOUT BY:" at 316.626,-48.823 h1.14
  text "or any information contained therein. TI and/or its licensors do not warrant that this design will meet" at 151.031,-51.477 h1.14
  text ".PRJ_Engineer" at 279.669,-52.76 h1.78
  text ".PCB_Layout" at 317.908,-52.76 h1.78
  text "the specifications, will be suitable for your application or fit for any particular purpose, or will operate in" at 151.031,-54.339 h1.14
  text ".Layer_Name" at 4.929,-55.046 h1.52
  text "ALTIUM DESIGNER VERSION:" at 316.626,-56.697 h1.14
  text "an implementation. TI and/or its licensors do not warrant that the design is production worthy. You should" at 151.031,-57.201 h1.14
  text "completely validate and test your design implementation to confirm the system functionality for your application." at 152.173,-60.062 h1.14
  text ".print_Scale" at 279.669,-60.083 h1.78
  text ".Application_BuildNumber" at 317.908,-60.083 h1.78
  text "1" at 9.065,-65.333 h1.78
  text "2" at 72.455,-65.333 h1.78
  text "3" at 135.685,-65.333 h1.78
  text "4" at 199.354,-65.333 h1.78
  text "5" at 262.828,-65.333 h1.78
  text "6" at 326.455,-65.333 h1.78
M10 Fab Notes:
  drawing of 173 lines, arcs and shapes, not listed
  text "DESIGN INFORMATION" at 304.675,124.266 h1.52
  text "MIN. TRACK WIDTH:" at 288.303,119.694 h1.52
  text "8" at 316.148,119.694 h1.52
  text "MIL" at 320.079,119.694 h1.52
  text "MIN. CLEARANCE:" at 288.303,116.341 h1.52
  text "0.2" at 314.624,116.341 h1.52
  text "mm" at 320.079,116.341 h1.52
  text "MIN. VIA PAD SIZE:" at 288.303,112.988 h1.52
  text "24" at 315.386,112.988 h1.52
  text "MIL" at 320.079,112.988 h1.52
  text "0.05mm (2MIL)" at 305.956,109.389 h1.52
  text "MINIMUM ANNULAR RING" at 279.941,109.28 h1.52
  text "EXTERNAL" at 323.94,109.28 h1.52
  text "PER" at 285.021,106.282 h1.52
  text "IPC-D-275 CLASS 2 LEVEL C" at 290.609,106.282 h1.52
  text "MIL, HOLES" at 328.41,103.43 h1.52
  text "+/-" at 318.442,103.412 h1.52
  text "+/-" at 340.133,103.412 h1.52
  text "REGISTRATION TOLERANCES:" at 279.941,103.285 h1.52
  text "METAL" at 310.415,103.285 h1.52
  text "5" at 325.051,103.285 h1.52
  text "3" at 346.209,103.285 h1.52
  text "MIL" at 349.162,103.285 h1.52
  text "+/-" at 340.133,100.415 h1.52
  text "HOLE SIZE TOLERANCE (UNLESS OTHERWISE SPECIFIED):" at 279.941,100.288 h1.52
  text "3" at 346.209,100.288 h1.52
  text "MIL" at 349.162,100.288 h1.52
  text "MATERIAL:" at 278.042,94.968 h1.52
  text "FR-4 High Tg" at 303.098,91.403 h1.52
  text "FR-408" at 288.735,91.186 h1.52
  text "OTHER" at 326.53,91.186 h1.52
  text "X" at 299.163,91.093 h1.52
  text "62 MIL (1.6mm) +/-10%" at 296.866,87.053 h1.52
  text "THICKNESS:" at 279.941,86.944 h1.52
  text "X" at 293.61,86.944 h1.52
  text "OTHER" at 329.502,86.944 h1.52
  text "TOLERANCE:" at 279.941,82.931 h1.52
  text "X" at 301.259,82.931 h1.52
  text "ANSI IPC-6012 TYPE 3 CLASS 2" at 306.008,82.931 h1.52
  text "OTHER +/-" at 306.007,78.968 h1.52
  text "BOW & TWIST:" at 279.941,74.98 h1.52
  text "X" at 301.259,74.98 h1.52
  text "ANSI IPC-6012 TYPE 3 CLASS 2" at 306.008,74.98 h1.52
  text "OTHER +/-" at 306.007,70.954 h1.52
  text "DRILLING:" at 278.042,67.437 h1.52
  text "REFERENCE:" at 279.941,64.465 h1.52
  text "X" at 296.406,64.465 h1.52
  text "AS SHOWN" at 301.156,64.465 h1.52
  text "X" at 319.291,64.465 h1.52
  text "NC_DRILL FILES" at 322.771,64.465 h1.52
  text "PTH COPPER THICKNESS:" at 279.941,60.452 h1.52
  text "X" at 308.649,60.452 h1.52
  text "20-30 um" at 312.129,60.452 h1.52
  text "OTHER" at 330.34,60.452 h1.52
  text "BOARD FINISH:" at 278.042,56.413 h1.52
  text "SILKSCREEN:" at 281.985,53.416 h1.52
  text "X" at 306.083,53.416 h1.52
  text "TOP" at 309.284,53.416 h1.52
  text "X" at 319.037,53.416 h1.52
  text "BOTTOM" at 322.263,53.416 h1.52
  text "SILKSCREEN COLOR:" at 281.985,49.174 h1.52
  text "X" at 306.057,49.174 h1.52
  text "WHITE" at 309.284,49.174 h1.52
  text "OTHER" at 322.263,49.174 h1.52
  text "X" at 309.385,45.13 h1.52
  text "GREEN" at 312.611,45.13 h1.52
  text "OTHER" at 328.308,45.13 h1.52
  text "SOLDER RESIST COLOR:" at 281.985,44.856 h1.52
  text "X" at 309.385,40.812 h1.52
  text "MATTE" at 312.611,40.812 h1.52
  text "SEMI-GLOSS" at 328.297,40.796 h1.52
  text "IMMERSION GOLD (ENIG)" at 304.991,36.024 h1.52
  text "ENEPIG" at 338.965,35.941 h1.52
  text "SURFACE FINISH:" at 278.042,35.915 h1.52
  text "X" at 300.243,35.915 h1.52
  text "IMM. TIN/SILVER OR EQUIV" at 286.412,31.927 h1.52
  text "OTHER" at 322.771,31.927 h1.52
  text "ARRAY/PANEL:" at 278.042,27.381 h1.52
  text "CUT AND TRIM PER M1 BOARD OUTLINE" at 304.991,27.272 h1.52
  text "N.C. ROUTE" at 304.991,23.418 h1.52
  text "X" at 322.238,23.418 h1.52
  text "V. SCORE" at 326.988,23.418 h1.52
  text "CERTIFICATION:" at 278.042,19.939 h1.52
  text "MATERIALS AND WORKMANSHIP FOR ALL PCBS" at 296.457,19.939 h1.52
  text "TO MEET OR EXCEED THE REQUIREMENTS OF:" at 296.457,17.449 h1.52
  text "X" at 286.97,13.982 h1.52
  text "ANSI IPC-A-600F CLASS ->" at 290.501,13.982 h1.52
  text "X" at 332.133,13.982 h1.52
  text "2" at 335.154,13.982 h1.52
  text "1" at 327.153,13.944 h1.52
  text "3" at 344.145,13.944 h1.52
  text "X" at 307.647,9.931 h1.52
  text "RoHS" at 311.125,9.931 h1.52
  text "OTHER" at 327.493,9.931 h1.52
  text "PER ORDER" at 337.579,9.931 h1.52
  text "ALL BOARDS MUST MEET OR EXCEED UL94-V0 REQUIREMENTS." at 278.741,5.724 h1.52
  text "PCB MUST BEAR THE UL94V-0 UL REGISTERED MATERIAL ID NUMBER" at 278.741,2.676 h1.52
  text "ADDITIONAL REQUIREMENTS:" at 278.042,-1.728 h1.52
  text "MICROSECTION:" at 279.941,-4.649 h1.52
  text "YES" at 302.947,-4.649 h1.52
  text "REQUIRED" at 324.829,-8.615 h1.52
  text "BARE BOARD ELEC. TEST:" at 279.941,-8.687 h1.52
  text "NONE" at 313.107,-8.687 h1.52
  text "X" at 321.603,-8.687 h1.52
  text "PER ORDER" at 339.865,-8.687 h1.52
  text ".Layer_Name" at 4.929,-55.046 h1.52
M11 Gerber Information:
  lines w0.254: -17.143,-56.866 150.497,-56.866 ; -17.143,-51.701 150.548,-51.701 ; -17.143,-46.537 -17.143,-62.031 84.584,-62.031 150.548,-62.031 150.548,-46.537 -17.13,-46.537 -17.13,-62.031 22.887,-62.031 ; 45.468,-62.031 45.468,-46.537 ; 77.65,-51.701 77.65,-46.537 ; 98.986,-51.701 98.986,-46.537 ; 114.784,-62.196 114.784,-57.044
  text "ALL ARTWORK VIEWED FROM TOP SIDE" at -15.53,-49.894 h1.52
  text "BOARD #:" at 47.373,-49.894 h1.52
  text ".PRJ_Number" at 61.229,-49.894 h1.52
  text "REV:" at 82.679,-49.894 h1.52
  text ".PCB_Rev" at 90.083,-49.894 h1.52
  text "SVN REV:" at 103.964,-49.894 h1.52
  text ".VersionControl_RevNumber" at 116.816,-49.894 h1.52
  text "LAYER NAME =" at -15.53,-55.046 h1.52
  text "TID #:" at 47.373,-55.058 h1.52
  text ".TID" at 61.229,-55.058 h1.52
  text "PLOT NAME =" at -15.53,-60.274 h1.52
  text ".plot_File_Name" at 4.929,-60.274 h1.52
  text "GENERATED    :" at 47.424,-60.274 h1.52
  text ".Print_Date" at 69.509,-60.274 h1.52
  text ".Print_Time" at 88.026,-60.274 h1.52
  text "TEXAS INSTRUMENTS" at 120.144,-60.274 h1.52
M12 Stackup:
  drawing of 191 lines, arcs and shapes, not listed
  text "Layer" at 238.948,165.642 h1.52
  text "Name" at 249.36,165.642 h1.52
  text "Material" at 272.976,165.642 h1.52
  text "Thickness" at 294.814,165.642 h1.52
  text "Constant" at 311.319,165.642 h1.52
  text "Board Layer Stack" at 325.794,165.642 h1.52
  text "1" at 238.948,162.594 h1.52
  text "Top Overlay" at 249.36,162.594 h1.52
  text "2" at 238.948,159.546 h1.52
  text "Top Solder" at 249.36,159.546 h1.52
  text "Solder Resist" at 272.976,159.546 h1.52
  text "0.40mil" at 294.814,159.546 h1.52
  text "3.5" at 311.319,159.546 h1.52
  text "3" at 238.948,156.498 h1.52
  text "Top Layer" at 249.36,156.498 h1.52
  text "Copper" at 272.976,156.498 h1.52
  text "1.40mil" at 294.814,156.498 h1.52
  text "4" at 238.948,153.45 h1.52
  text "Dielectric1" at 249.36,153.45 h1.52
  text "FR-4" at 272.976,153.45 h1.52
  text "59.20mil" at 294.814,153.45 h1.52
  text "4.8" at 311.319,153.45 h1.52
  text "5" at 238.948,150.402 h1.52
  text "Bottom Layer" at 249.36,150.402 h1.52
  text "Copper" at 272.976,150.402 h1.52
  text "1.40mil" at 294.814,150.402 h1.52
  text "6" at 238.948,147.354 h1.52
  text "Bottom Solder" at 249.36,147.354 h1.52
  text "Solder Resist" at 272.976,147.354 h1.52
  text "0.40mil" at 294.814,147.354 h1.52
  text "3.5" at 311.319,147.354 h1.52
  text "7" at 238.948,144.306 h1.52
  text "Bottom Overlay" at 249.36,144.306 h1.52
M13 Component Bodies Top:
  text ".Layer_Name" at 4.929,-55.046 h1.52
M14 Component Bodies Bottom:
  text ".Layer_Name" at 4.929,-55.046 h1.52
M15 Courtyards Top:
  text ".Layer_Name" at 4.929,-55.046 h1.52
M16 Courtyards Bottom:
  text ".Layer_Name" at 4.929,-55.046 h1.52
Drill Drawing:
  lines w0.254: 125.81,36.742 126.161,36.742 126.512,36.391 126.863,36.742 127.214,36.742 126.863,37.093 127.214,37.444 126.863,37.444 126.512,37.795 126.161,37.444 125.81,37.444 126.161,37.093 125.81,36.742 ; 125.81,40.952 127.214,40.952 126.512,39.549 125.81,40.952 ; 125.81,43.408 126.512,42.707 127.214,43.408 126.512,44.11 125.81,43.408 ; 125.81,45.864 125.81,46.215 126.161,46.566 125.81,46.917 125.81,47.268 126.161,47.268 126.512,46.917 126.863,47.268 127.214,47.268 127.214,46.917 126.863,46.566 127.214,46.215 127.214,45.864 126.863,45.864 126.512,46.215 126.161,45.864 125.81,45.864 ; 125.81,49.022 126.512,49.373 127.214,49.022 126.863,49.724 127.214,50.425 126.512,50.075 125.81,50.425 126.161,49.724 125.81,49.022
  lines w0.305: 124.538,35.444 206.618,35.444 ; 124.538,51.232 206.618,51.232 ; 133.12,32.286 133.12,54.39 ; 141.553,32.286 141.553,54.39 ; 157.721,32.286 157.721,54.39 ; 164.303,32.286 164.303,54.39 ; 173.832,32.286 173.832,54.39 ; 192.23,32.286 192.23,54.39 ; 124.538,32.286 206.618,32.286 206.618,54.39 124.538,54.39 124.538,32.286
  text "Symbol" at 126.433,52.18 h1.83
  text "Quantity" at 134.067,52.18 h1.83
  text "Finished Hole Size" at 142.5,52.18 h1.83
  text "Plated" at 158.669,52.18 h1.83
  text "Hole Type" at 165.251,52.18 h1.83
  text "Drill Layer Pair" at 174.78,52.18 h1.83
  text "Hole Tolerance" at 193.178,52.18 h1.83
  text "5" at 134.067,49.022 h1.52
  text "7.87mil (0.200mm)" at 142.5,49.022 h1.52
  text "PTH" at 158.669,49.022 h1.52
  text "Round" at 165.251,49.022 h1.52
  text "Top Layer - Bottom Layer" at 174.78,49.022 h1.52
  text "88" at 134.067,45.864 h1.52
  text "8.00mil (0.203mm)" at 142.5,45.864 h1.52
  text "PTH" at 158.669,45.864 h1.52
  text "Round" at 165.251,45.864 h1.52
  text "Top Layer - Bottom Layer" at 174.78,45.864 h1.52
  text "7" at 134.067,42.707 h1.52
  text "27.95mil (0.710mm)" at 142.5,42.707 h1.52
  text "PTH" at 158.669,42.707 h1.52
  text "Round" at 165.251,42.707 h1.52
  text "Top Layer - Bottom Layer" at 174.78,42.707 h1.52
  text "6" at 134.067,39.549 h1.52
  text "39.37mil (1.000mm)" at 142.5,39.549 h1.52
  text "PTH" at 158.669,39.549 h1.52
  text "Round" at 165.251,39.549 h1.52
  text "Top Layer - Bottom Layer" at 174.78,39.549 h1.52
  text "2" at 134.067,36.391 h1.52
  text "43.31mil (1.100mm)" at 142.5,36.391 h1.52
  text "PTH" at 158.669,36.391 h1.52
  text "Round" at 165.251,36.391 h1.52
  text "Top Layer - Bottom Layer" at 174.78,36.391 h1.52
  text "108 Total" at 134.067,33.233 h1.52
  text ".Layer_Name" at 4.929,-55.046 h1.52
M17 Embedded Cavity:
  text ".Layer_Name" at 4.929,-55.046 h1.52
M18 Embedded Assembly:
  text ".Layer_Name" at 4.929,-55.046 h1.52
M19 Embedded Keepout:
  text ".Layer_Name" at 4.929,-55.046 h1.52

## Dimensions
-9.726,-43.4 to 15.674,-43.4 on M2 Board Dimensions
